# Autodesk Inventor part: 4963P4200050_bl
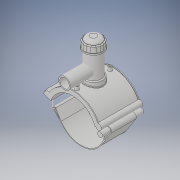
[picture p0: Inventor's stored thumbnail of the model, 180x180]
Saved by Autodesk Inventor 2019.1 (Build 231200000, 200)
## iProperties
Created: 2017-07
Part Number: 4963P4200050_bl
Material: Generic
Document SubType Name: Modeling
Designer: KIM
Density: 1 g/cm^3
Appearance: Default
Author: KIM
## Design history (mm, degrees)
derived "4963P4.ipt"
feature "Solid1::4963P4.ipt" dims "ScaleForDerivedMember" = 10
feature "Solid2::4963P4.ipt" dims "ScaleForDerivedMember" = 10
feature "Solid3::4963P4.ipt" dims "ScaleForDerivedMember" = 10
tag "TaggingFeature1"
body "Solid1"
body "Solid2"
body "Solid3"
other parameters: "B_" = 202 [user parameter], "L_" = 176 [user parameter], "d_t" = 6 [user parameter], "H_2" = 177 [user parameter], "H_1" = 64 [user parameter], "H_" = 123 [user parameter], "d1" = 232 [user parameter], "d148" = 3 [user parameter], "d160" = 3 [user parameter], "d169" = 3 [user parameter], "d192" = 6.4 [user parameter], "d2" = 262.6 [user parameter], "d4" = 176 [user parameter], "d5" = 0 [user parameter], "d6" = 0.1 [user parameter], "d8" = 0 [user parameter], "d19" = 6 [user parameter], "d20" = 6 [user parameter], "d21" = 105.6 [user parameter], "d23" = 0 [user parameter], "d24" = 52.8 [user parameter], "d26" = 0 [user parameter], "d27" = 3 [user parameter], "d28" = 3 [user parameter], "d29" = 3 [user parameter], "d30" = 66.66667 [user parameter], "d31" = 6 [user parameter], "d32" = 0 [user parameter], "d33" = 0 [user parameter], "d34" = 0.6 [user parameter], "d40" = 120.64 [user parameter], "d43" = 0 [user parameter], "d45" = 0 [user parameter], "d47" = 221.6 [user parameter], "d70" = 15 [user parameter], "d72" = 0 [user parameter], "d73" = 6 [user parameter], "d75" = 5 [user parameter], "d76" = 0 [user parameter], "d79" = 15 [user parameter], "d80" = 70.4 [user parameter], "d82" = 5 deg [user parameter], "d84" = 4 [user parameter], "d85" = 14 [user parameter], "d86" = 0 [user parameter], "d87" = 3 [user parameter], "d88" = 0 [user parameter], "d89" = 1 [user parameter], "d90" = 1 [user parameter], "d91" = 140.8 [user parameter], "d92" = 0 [user parameter], "d93" = 0.5 [user parameter], "d94" = 105.26316 [user parameter], "d96" = 236.64 [user parameter], "d97" = 3.52 [user parameter], "d98" = 0 [user parameter], "d102" = 2 [user parameter], "d120" = 140 deg [user parameter], "d121" = 24.228 [user parameter], "d122" = 20 deg [user parameter], "d123" = 464 [user parameter], "d124" = 139.2 [user parameter], "d126" = 0 [user parameter], "d143" = 206 [user parameter], "d145" = 24.61538 [user parameter], "d149" = 3 [user parameter], "d150" = 27.07692 [user parameter], "d153" = 176 [user parameter], "d154" = 0 [user parameter], "d156" = 116 [user parameter], "d157" = 160 deg [user parameter], "d159" = 6.4 [user parameter], "d161" = 3 [user parameter], "d162" = 105.6 [user parameter], "d163" = 0 [user parameter], "d168" = 113.17073 [user parameter], "d170" = 3 [user parameter], "d172" = 0 [user parameter], "d173" = 1 [user parameter], "d176" = 20 deg [user parameter], "d177" = 14 [user parameter], "d178" = 32 [user parameter], "d180" = 0 [user parameter], "d183" = 12.8 [user parameter], "d184" = 11.2 [user parameter], "d185" = 57.2 [user parameter], "d186" = 57.2 [user parameter], "d187" = 116 [user parameter], "d188" = 9.6 [user parameter], "d189" = 14 [user parameter], "d190" = 0 [user parameter], "d191" = 174 [user parameter], "d193" = 6.4 [user parameter], "d194" = 6.16 [user parameter], "d195" = 90 deg [user parameter], "d197" = 0 [user parameter], "d199" = 0 [user parameter], "d200" = 16 [user parameter], "d202" = 0 [user parameter], "d203" = 177 [user parameter], "d204" = 76 [user parameter], "d205" = 56 [user parameter], "d206" = 68 [user parameter], "d207" = 132.75 [user parameter], "d208" = 138.06 [user parameter], "d209" = 164.61 [user parameter], "d210" = 68.8 [user parameter], "d212" = 64 [user parameter], "d213" = 35.1 [user parameter], "d216" = 0 [user parameter], "d219" = 4 [user parameter], "d224" = 0 [user parameter], "d225" = 64 [user parameter], "d228" = 123 [user parameter], "d230" = 4 [user parameter]
